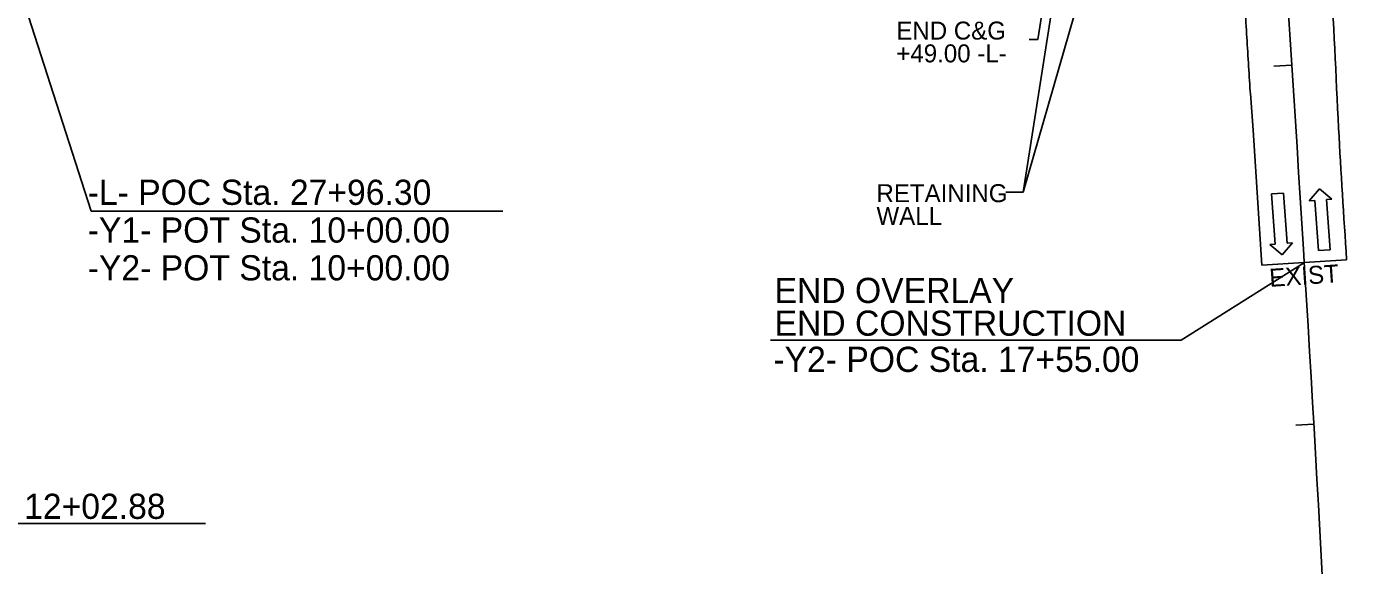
# Model space of a CAD drawing. Extents: x 1616561 to 1622460, y 896726 to 899651.
# Drawn here: x 1619580.2 to 1619947, y 897774.5 to 897924.5 of the extents above; entities that cross this region are included whole.
import ezdxf

# ---------------------------------------------------------------- set-up
doc = ezdxf.new("R2010")
doc.units = 0
for name, color, linetype in [('Prop Conc Curb and Gutter', 7, 'Continuous'), ('Prop Dimension', 7, 'Continuous'), ('Prop DSN Text', 7, 'Continuous'), ('Prop Lane Arrow CELL', 7, 'Continuous'), ('Prop Superelevation  Arrow CELL', 7, 'Continuous'), ('Prop Terminator CELL', 7, 'Continuous'), ('Sheet Cutting Line CELL', 7, 'Continuous'), ('Sheet North Arrow CELL', 7, 'Continuous')]:
    doc.layers.add(name, color=color, linetype=linetype)

msp = doc.modelspace()

# ---------------------------------------------------------------- linework, layer by layer
at = {"layer": 'Prop Conc Curb and Gutter'}
for p, q in [((1619920.26, 897905.81), (1619920.19, 897906.37)), ((1619947, 897859.54), (1619923.45, 897858.01))]:
    msp.add_line(p, q, dxfattribs=at)
msp.add_lwpolyline([(1619923.45, 897858.01), (1619921.05, 897895.58), (1619920.26, 897905.81)], dxfattribs=at)
for points in [[(1619926.95, 898133.76), (1619927.27, 898129.8), (1619930.05, 898096.53), (1619932.69, 898064.69), (1619935.3, 898031.6), (1619938.16, 897995.71), (1619939.79, 897970.86), (1619940.42, 897963.24), (1619941.13, 897955.62), (1619942.39, 897940.38), (1619944.78, 897896.12), (1619947, 897859.54)], [(1619920.19, 897906.37), (1619919.21, 897922.34), (1619918.22, 897939.23), (1619917.12, 897956.56)]]:
    msp.add_spline(points, degree=3, dxfattribs=at)
at = {"layer": 'Prop Dimension'}
for p, q in [((1619857.08, 897878.31), (1619888.27, 898076.82)), ((1619857.08, 897878.31), (1619893.5, 898004.21)), ((1619852.28, 897878.33), (1619857.08, 897878.31))]:
    msp.add_line(p, q, dxfattribs=at)
at = {"layer": 'Prop DSN Text'}
for p, q in [((1619861.24, 897920.78), (1619875.99, 898018.49)), ((1619858.75, 897920.79), (1619861.24, 897920.78))]:
    msp.add_line(p, q, dxfattribs=at)
at = {"layer": 'Prop Lane Arrow CELL'}
for p, q in [((1619926.15, 897877.84), (1619929.44, 897878.09)), ((1619927.19, 897863.88), (1619926.15, 897877.84)), ((1619929.44, 897878.09), (1619930.49, 897864.13)), ((1619936.64, 897875.94), (1619939.49, 897879.31)), ((1619939.49, 897879.31), (1619942.92, 897876.41)), ((1619938.13, 897876.05), (1619936.64, 897875.94)), ((1619939.18, 897862.09), (1619938.13, 897876.05)), ((1619942.92, 897876.41), (1619941.42, 897876.3)), ((1619941.42, 897876.3), (1619942.47, 897862.34)), ((1619925.7, 897863.77), (1619927.19, 897863.88)), ((1619929.13, 897860.87), (1619925.7, 897863.77)), ((1619931.98, 897864.24), (1619929.13, 897860.87)), ((1619930.49, 897864.13), (1619931.98, 897864.24)), ((1619942.47, 897862.34), (1619939.18, 897862.09))]:
    msp.add_line(p, q, dxfattribs=at)
at = {"layer": 'Prop Superelevation  Arrow CELL'}
for p, q in [((1619931.77, 897913.67), (1619926.78, 897913.34)), ((1619937.88, 897813.86), (1619932.89, 897813.57))]:
    msp.add_line(p, q, dxfattribs=at)
at = {"layer": 'Prop Terminator CELL'}
for p, q in [((1619920.26, 897905.81), (1619920.19, 897906.37)), ((1619947, 897859.54), (1619923.45, 897858.01))]:
    msp.add_line(p, q, dxfattribs=at)
msp.add_lwpolyline([(1619923.45, 897858.01), (1619921.05, 897895.58), (1619920.26, 897905.81)], dxfattribs=at)
for points in [[(1619926.95, 898133.76), (1619927.27, 898129.8), (1619930.05, 898096.53), (1619932.69, 898064.69), (1619935.3, 898031.6), (1619938.16, 897995.71), (1619939.79, 897970.86), (1619940.42, 897963.24), (1619941.13, 897955.62), (1619942.39, 897940.38), (1619944.78, 897896.12), (1619947, 897859.54)], [(1619920.19, 897906.37), (1619919.21, 897922.34), (1619918.22, 897939.23), (1619917.12, 897956.56)]]:
    msp.add_spline(points, degree=3, dxfattribs=at)
at = {"layer": 'Sheet Cutting Line CELL'}
msp.add_arc((1606187.46, 897021.41), 13773.24, 2.612111, 4.508639, dxfattribs=at)
at = {"layer": 'Sheet North Arrow CELL'}
for p, q in [((1619528.74, 898088.46), (1619598.19, 897873.05)), ((1619598.19, 897873.05), (1619712.5, 897873.05)), ((1619901.04, 897837.17), (1619935.33, 897858.78)), ((1619786.88, 897837.17), (1619901.04, 897837.17)), ((1619522.84, 897786.18), (1619629.95, 897786.18))]:
    msp.add_line(p, q, dxfattribs=at)

# ---------------------------------------------------------------- texts
at = {"layer": 'Prop Dimension'}
for s, p in [('RETAINING ', (1619816.37, 897875.56)), ('WALL', (1619816.37, 897869.23))]:
    msp.add_text(s, height=5, dxfattribs=at).set_placement(p)
msp.add_text('EXIST', height=5, rotation=3.8599, dxfattribs=at).set_placement((1619925.69, 897851.99))
at = {"layer": 'Prop DSN Text'}
for s, p in [('END C&G', (1619821.88, 897920.78)), ('+49.00 -L-', (1619821.88, 897914.44))]:
    msp.add_text(s, height=5, dxfattribs=at).set_placement(p)
at = {"layer": 'Sheet North Arrow CELL'}
for s, p in [('-L- POC Sta. 27+96.30', (1619597.19, 897874.81)), ('-Y1- POT Sta. 10+00.00', (1619597.19, 897864.31)), ('-Y2- POT Sta. 10+00.00 ', (1619597.19, 897853.81)), ('END OVERLAY', (1619788.03, 897847.51)), ('END CONSTRUCTION', (1619788.03, 897838.41)), ('-Y1- PC Sta.  12+02.88', (1619521.78, 897787.47))]:
    msp.add_text(s, height=7, rotation=360, dxfattribs=at).set_placement(p)
msp.add_text('-Y2- POC Sta. 17+55.00', height=7, dxfattribs=at).set_placement((1619787.71, 897828.35))

doc.saveas('drawing.dxf')
